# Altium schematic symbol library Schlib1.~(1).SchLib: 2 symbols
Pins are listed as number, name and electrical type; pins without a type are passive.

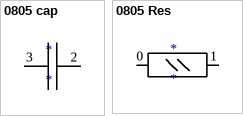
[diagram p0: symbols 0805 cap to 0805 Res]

## 0805 cap
designator *
pins: 2, 3

## 0805 Res
designator *
pins: 0, 1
